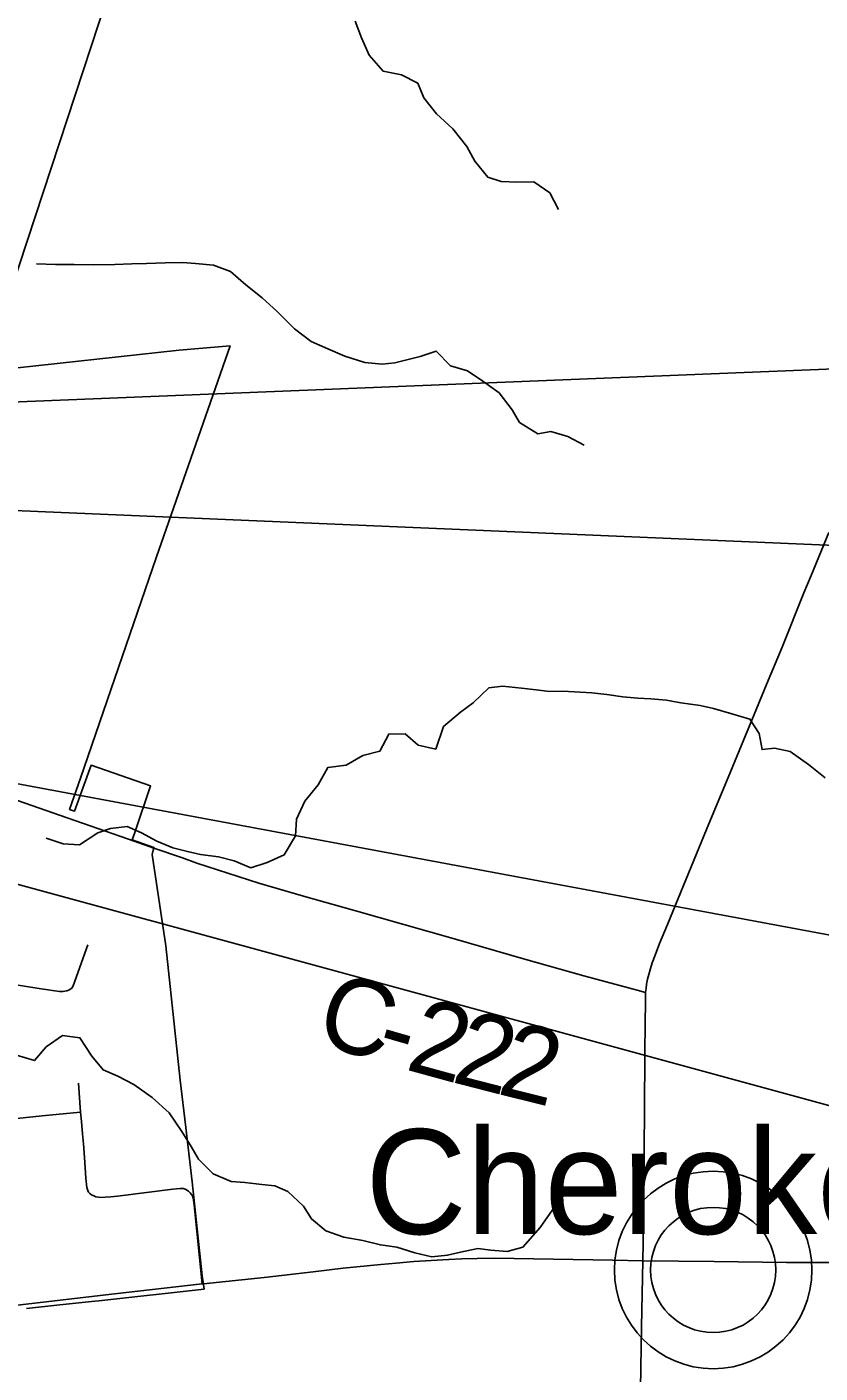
# Model space of a CAD drawing. Extents: x -5.9 to 34, y 0 to 22.
# Drawn here: x 7.523 to 8.718, y 16.281 to 18.309 of the extents above; entities that cross this region are included whole.
import ezdxf

# ---------------------------------------------------------------- set-up
doc = ezdxf.new("R2010")
doc.units = 0
for name, color, linetype in [('GM_X_City_Street', 7, 'Continuous'), ('GM_X_Corporation', 7, 'Continuous'), ('GM_X_County_Road', 7, 'Continuous'), ('GM_X_County_Road_Text', 7, 'Continuous'), ('GM_X_Minor_River', 7, 'Continuous'), ('GM_X_Rail_Line', 7, 'Continuous'), ('GM_X_State_Route', 7, 'Continuous'), ('GM_X_Unincorporated', 7, 'Continuous'), ('GM_X_Unincorporated_Location', 7, 'Continuous'), ('GM_X_Unincorporated_Text', 7, 'Continuous'), ('SH_Text', 7, 'Continuous')]:
    doc.layers.add(name, color=color, linetype=linetype)

msp = doc.modelspace()

# ---------------------------------------------------------------- linework, layer by layer
at = {"layer": 'GM_X_City_Street'}
for points in [[(7.5826, 16.8568), (7.5856, 16.8577), (7.5881, 16.8591), (7.5904, 16.8609), (7.5923, 16.8641), (7.6145, 16.926)], [(7.3121, 16.9057), (7.3213, 16.9034), (7.3645, 16.8924), (7.3786, 16.889), (7.3933, 16.8856), (7.4068, 16.8825), (7.426, 16.8787), (7.444, 16.8753), (7.4638, 16.8722), (7.4841, 16.8691), (7.5442, 16.86), (7.5716, 16.8559), (7.5745, 16.8557), (7.5771, 16.8557), (7.5796, 16.8561), (7.5826, 16.8568)], [(7.6173, 16.5512), (7.6157, 16.5536), (7.6146, 16.5561), (7.6132, 16.5607), (7.6113, 16.5743), (7.6093, 16.6054), (7.6077, 16.626), (7.6066, 16.6415), (7.6048, 16.6599), (7.6035, 16.6737), (7.6002, 16.7177)], [(7.2179, 16.6343), (7.2312, 16.6357), (7.3475, 16.648), (7.4417, 16.6581), (7.4769, 16.6616), (7.5024, 16.6641), (7.5509, 16.6689), (7.588, 16.6723), (7.6035, 16.6737)], [(7.6173, 16.5512), (7.62, 16.5492), (7.6233, 16.5478), (7.6267, 16.5465), (7.6307, 16.5459), (7.6351, 16.5454), (7.6406, 16.5457), (7.649, 16.5463), (7.6591, 16.5472), (7.7426, 16.558), (7.7482, 16.5586), (7.7537, 16.559), (7.7586, 16.5587), (7.7621, 16.5576), (7.7663, 16.5549)], [(7.7868, 16.4153), (7.7748, 16.5345), (7.7732, 16.545), (7.7722, 16.5477), (7.7709, 16.5497), (7.7685, 16.5526), (7.7663, 16.5549)]]:
    msp.add_lwpolyline(points, dxfattribs=at)
at = {"layer": 'GM_X_Corporation'}
msp.add_lwpolyline([(7.4759, 17.7917), (7.7523, 17.822), (7.8289, 17.8284), (7.7181, 17.5107), (7.6033, 17.1773), (7.587, 17.13), (7.5944, 17.1276), (7.6194, 17.1967), (7.709, 17.1654), (7.6853, 17.0955), (7.6812, 17.0843), (7.7142, 17.0729), (7.7115, 17.0621), (7.732, 16.9245), (7.7539, 16.7222), (7.7622, 16.6509), (7.7715, 16.5688), (7.7866, 16.4276), (7.7896, 16.4075), (7.6311, 16.3898), (7.6251, 16.3892), (7.5723, 16.3836), (7.5218, 16.3783)], dxfattribs=at)
at = {"layer": 'GM_X_County_Road'}
msp.add_line((7.6845, 17.082), (7.7142, 17.0717), dxfattribs=at)
for points in [[(8.451, 16.45), (8.4527, 16.532), (8.4537, 16.6869), (8.4546, 16.8188), (8.4548, 16.8289), (8.455, 16.8388), (8.4553, 16.8535), (8.4553, 16.8541), (8.4559, 16.8605), (8.4568, 16.8668), (8.4583, 16.8743), (8.4599, 16.8812), (8.4627, 16.8903), (8.4653, 16.8989), (8.4695, 16.9106), (8.4763, 16.9279), (8.4881, 16.9566), (8.532, 17.0634), (8.5507, 17.1082), (8.5796, 17.1782), (8.5964, 17.2183), (8.6154, 17.2643), (8.6375, 17.3184), (8.6609, 17.3746), (8.6939, 17.4563), (8.705, 17.4827), (8.7313, 17.5471)], [(7.5083, 17.1437), (7.5835, 17.1172), (7.664, 17.0891), (7.6845, 17.082)], [(7.7142, 17.0717), (7.757, 17.0569), (7.7787, 17.049), (7.8721, 17.0191), (7.9396, 16.9994), (8.0162, 16.9777), (8.1651, 16.9358), (8.2749, 16.904), (8.3621, 16.8791), (8.4424, 16.8576), (8.4553, 16.8541)], [(8.4476, 16.2578), (8.4489, 16.3505), (8.451, 16.45)]]:
    msp.add_lwpolyline(points, dxfattribs=at)
at = {"layer": 'GM_X_Minor_River'}
for points in [[(8.0176, 18.3176), (8.027, 18.2924), (8.0387, 18.2664), (8.0595, 18.2425), (8.0874, 18.2367), (8.1121, 18.2241), (8.1208, 18.202), (8.1401, 18.1781), (8.1647, 18.1557), (8.1855, 18.1288), (8.198, 18.1066), (8.2173, 18.0827), (8.2376, 18.0763), (8.261, 18.0752), (8.2868, 18.0755), (8.3107, 18.0591), (8.3239, 18.0339)], [(7.537, 17.9523), (7.5657, 17.951), (7.5937, 17.9513), (7.6225, 17.9508), (7.655, 17.951), (7.6808, 17.9521), (7.7027, 17.9525), (7.7308, 17.9536), (7.7573, 17.9539), (7.7769, 17.9528), (7.8041, 17.95), (7.8297, 17.9405), (7.8528, 17.9204), (7.8775, 17.901), (7.8998, 17.8801), (7.9259, 17.8539), (7.9513, 17.8352), (7.9761, 17.8242), (8.0017, 17.8131), (8.0318, 17.8035), (8.0582, 17.8008), (8.0772, 17.8028), (8.1152, 17.8127), (8.1395, 17.8207), (8.1611, 17.7983), (8.1867, 17.791), (8.2099, 17.7755), (8.2346, 17.7576), (8.2539, 17.7322), (8.2649, 17.7131), (8.2926, 17.6959), (8.3124, 17.6994), (8.338, 17.6921), (8.3627, 17.6788)], [(7.5515, 17.0868), (7.5771, 17.078), (7.6021, 17.0768), (7.6296, 17.0946), (7.6486, 17.1011), (7.6737, 17.1044), (7.6955, 17.095), (7.7187, 17.0824), (7.7428, 17.0721), (7.7646, 17.0665), (7.7842, 17.0623), (7.8114, 17.0588), (7.8348, 17.0524), (7.8604, 17.0421), (7.8847, 17.05), (7.9106, 17.0617), (7.9277, 17.0903), (7.9289, 17.1153), (7.9415, 17.1424), (7.9615, 17.1671), (7.9764, 17.1934), (8.0037, 17.1968), (8.0289, 17.2115), (8.0547, 17.2179), (8.068, 17.2435), (8.093, 17.2439), (8.1124, 17.2268), (8.1388, 17.2211), (8.1507, 17.255), (8.176, 17.2766), (8.1952, 17.2907), (8.219, 17.3131), (8.2395, 17.3158), (8.2682, 17.313), (8.2901, 17.3104), (8.3105, 17.3077), (8.3302, 17.3082), (8.374, 17.3059), (8.3967, 17.3032), (8.4209, 17.2998), (8.4435, 17.2979), (8.4632, 17.2968), (8.4866, 17.2949), (8.5085, 17.2907), (8.5372, 17.2865), (8.5576, 17.2823), (8.5854, 17.2742), (8.6125, 17.2662), (8.6266, 17.2447), (8.6307, 17.2203), (8.6497, 17.2223), (8.673, 17.2174), (8.7007, 17.1979), (8.7261, 17.1777)], [(7.5068, 16.7596), (7.5339, 16.7516), (7.5517, 16.7725), (7.5762, 16.7896), (7.6026, 16.7861), (7.6203, 16.7584), (7.6374, 16.7377), (7.6599, 16.7282), (7.684, 16.7156), (7.7116, 16.6962), (7.737, 16.673), (7.7562, 16.6446), (7.7702, 16.6223), (7.7813, 16.6031), (7.8036, 16.5808), (7.8307, 16.5697), (7.8511, 16.5678), (7.8768, 16.5651), (7.8964, 16.5632), (7.916, 16.5546), (7.9398, 16.5322), (7.9516, 16.513), (7.9733, 16.4952), (8.0003, 16.4856), (8.029, 16.4805), (8.0554, 16.474), (8.0803, 16.4706), (8.1074, 16.4618), (8.1331, 16.456), (8.1566, 16.4587), (8.1763, 16.4629), (8.2021, 16.4685), (8.2218, 16.4659), (8.2467, 16.464), (8.2703, 16.4704), (8.2965, 16.5003), (8.3151, 16.5266), (8.3352, 16.5528)]]:
    msp.add_lwpolyline(points, dxfattribs=at)
at = {"layer": 'GM_X_Rail_Line'}
msp.add_lwpolyline([(8.6569, 21), (8.5857, 20.9088), (8.513, 20.7995), (8.4462, 20.6951), (8.3598, 20.5123), (8.2981, 20.3347), (8.2297, 20.1139), (7.7274, 18.6082), (7.2699, 17.2177), (7.0415, 16.5495)], dxfattribs=at)
at = {"layer": 'GM_X_State_Route'}
msp.add_line((7.7868, 16.4153), (7.7888, 16.4155), dxfattribs=at)
for points in [[(7.7888, 16.4155), (7.8802, 16.425), (7.9543, 16.4336), (7.9991, 16.4387), (8.0563, 16.4446), (8.0793, 16.4465), (8.1058, 16.4488), (8.1318, 16.4507), (8.1584, 16.4522), (8.1783, 16.4529), (8.2012, 16.4534), (8.2267, 16.4539), (8.257, 16.4535), (8.4055, 16.4508), (8.451, 16.45), (8.5584, 16.4488), (8.6677, 16.4477), (8.7361, 16.4477), (8.9187, 16.4465), (9, 16.4458)], [(7.2497, 16.3582), (7.2604, 16.3575), (7.2644, 16.3577), (7.3856, 16.3698), (7.486, 16.3808), (7.5084, 16.3833), (7.6545, 16.4001), (7.7868, 16.4153)]]:
    msp.add_lwpolyline(points, dxfattribs=at)
at = {"layer": 'GM_X_Unincorporated'}
for radius in [0.1488, 0.0943]:
    msp.add_circle((8.5571, 16.4362), radius, dxfattribs=at)
at = {"layer": 'GM_X_Unincorporated_Location'}
msp.add_line((8.5571, 16.4362), (8.5571, 16.4362), dxfattribs=at)
at = {"layer": 'SH_Text'}
for points in [[(9.6717, 17.8317), (5.5354, 17.6641), (9.6717, 17.4879)], [(9.6586, 16.4313), (5.7532, 17.4957), (9.6586, 16.7683)]]:
    msp.add_lwpolyline(points, close=True, dxfattribs=at)

# ---------------------------------------------------------------- texts
at = {"layer": 'GM_X_County_Road_Text'}
for s, rotation, p in [('C', 343.3748, (7.954, 16.7793)), ('2', 344.6997, (8.091, 16.7388)), ('2', 345.6002, (8.1604, 16.7199)), ('-', 343.902, (8.0445, 16.7522)), ('2', 346.0641, (8.2292, 16.7022))]:
    msp.add_text(s, height=0.1136, rotation=rotation, dxfattribs=at).set_placement(p)
at = {"layer": 'GM_X_Unincorporated_Text'}
msp.add_text('Cherokee', height=0.15795, rotation=0, dxfattribs=at).set_placement((8.0329, 16.4903))

doc.saveas('drawing.dxf')
